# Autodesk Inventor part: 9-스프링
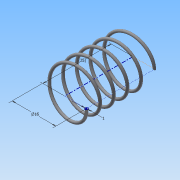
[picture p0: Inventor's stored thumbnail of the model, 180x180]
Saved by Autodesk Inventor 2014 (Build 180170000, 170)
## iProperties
Created: 2015-06
Part Number: 9-스프링
Material: 강철, 연강
Document SubType Name: Modeling
Designer: Administrator
Density: 7.86 g/cm^3
Appearance: 강철
Mass: 1.52604 g
Surface Area: 7.87202 cm^2
Volume: 0.194153 cm^3
Author: Administrator
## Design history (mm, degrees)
sketch "스케치1"
  geometry: L1 (0, 0)-(8, 0); L2 (8, 0)-(8, 14.5); L3 (8, 14.5)-(0, 14.5); L4 (0, 14.5)-(0, 0); C1 r 0.5 at (8, 0)
  constraints: 8 end point, 2 parallel, 1 centre point, 1 coincident, 1 horizontal, 1 perpendicular
  dimensions: "d0" = 14.5 distance of L3.end L1.start (derived); "d1" = 16 diameter of L1.end L4; "d2" = 1 diameter of C1
feature "코일1" sketch "스케치1" pitch "d3" = 10; turns "d5" = 5; dims "d4" = 14.5 (= d0), "d6" = 0, angle "d7" = 90 deg, angle "d8" = 90 deg, "d9" = 0, "d10" = 0
sketch "스케치2"
  geometry: L1 (15.5, -10)-(-15.5, -10); L2 (-15.5, -10)-(-15.5, 0); L3 (-15.5, 0)-(15.5, 0); L4 (15.5, 0)-(15.5, -10); L5 (-20, 24.5)-(20, 24.5); L6 (20, 24.5)-(20, 14.5); L7 (20, 14.5)-(-20, 14.5); L8 (-20, 14.5)-(-20, 24.5); 3 further points
  constraints: 16 end point, 4 parallel, 2 horizontal, 2 midpoint, 2 perpendicular, 1 coincident, 1 vertical alignment
  dimensions: "d11" = 10 distance of L3.end L1.start; "d12" = 31 distance of L1.start L1.end; "d13" = 14.5 distance between parallel lines of L3 L7 (= d0); "d14" = 10 distance of L5.end L6.end; "d15" = 40 distance of L5.start L5.end
extrude "돌출1" cut sketch "스케치2" stored distance "d16" = 0; taper "d17" = 0 deg
node "솔리드1"
